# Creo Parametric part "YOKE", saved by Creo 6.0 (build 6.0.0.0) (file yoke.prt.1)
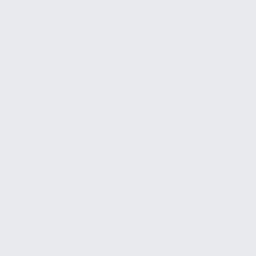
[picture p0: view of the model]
Units: millimeter Newton Second (mmNs); MM, TONNE, SECS

Created from: MMNS_PART_SOLID.PRT

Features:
  1. datum plane "RIGHT"
  2. datum plane "TOP"
  3. datum plane "FRONT"
  4. coordinate system
  5. sketch "Sketch 1"
  6. extrusion "Extrude 1"
  7. sketch "Sketch 2"
  8. extrusion "Extrude 2"
  9. mirror "Mirror 1"
  10. extrusion "Extrude 2 (2)"
  11. sketch "Sketch 3"
  12. extrusion "Extrude 3"
  13. sketch "Sketch 4", "A_4"
  14. protrusion "Helical Sweep 1"
  15. mirror "Mirror 2"
  16. protrusion "Helical Sweep 1 (2)"
  17. datum axis "A_5"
